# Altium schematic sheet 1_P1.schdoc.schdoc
size 309 x 223 mm; Symbol: Sheet-Symbol_A4; Device: Sheet-Symbol_A4; Company: 嘉立创EDA; Version: V1.0; Page Size: A4; @Project Name: 简易酒驾报警电路; @Page Count: 1; @Update Date: 2024-03-24; @Create Date: 2024-03-24; @Schematic Name: Schematic1; @Page No: 1; @Page Name: P1
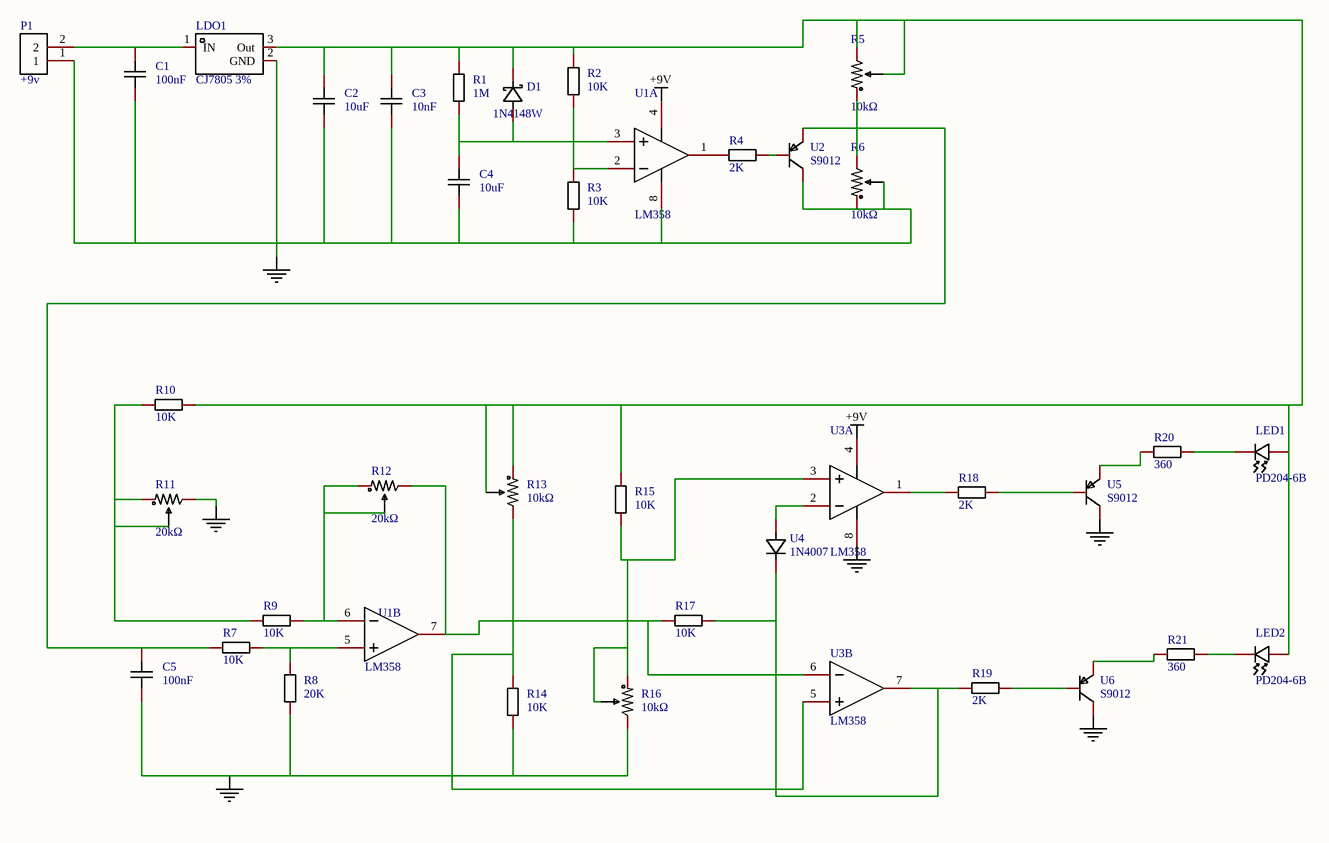
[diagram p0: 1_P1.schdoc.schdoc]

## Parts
C1  100nF  [C0603]
C2  10uF  [C0603]
C3  10nF  [C0603]
C4  10uF  [C0603]
C5  100nF  [C0603]
D1  1N4148W  [SOD-123_L2.7-W1.6-LS3.7-FD]
LDO1  CJ7805 3%  [TO-252-2_L6.6-W6.1-P4.58-LS10.1-BR-CW]
LED1  PD204-6B  [LED-TH_BD3.1-P2.54-FD]
LED2  PD204-6B  [LED-TH_BD3.1-P2.54-FD]
P1  +9v  [CONN-TH_2P-P5.00_WJ500V-5.08-2P]
R1  1M  [R0603]
R2  10K  [R0603]
R3  10K  [R0603]
R4  2K  [R0603]
R5  10kΩ  [RES-ADJ-TH_3362P]
R6  10kΩ  [RES-ADJ-TH_3362P]
R7  10K  [R0603]
R8  20K  [R0603]
R9  10K  [R0603]
R10  10K  [R0603]
R11  20kΩ  [RES-ADJ-TH_3362P]
R12  20kΩ  [RES-ADJ-TH_3362P]
R13  10kΩ  [RES-ADJ-TH_3362P]
R14  10K  [R0603]
R15  10K  [R0603]
R16  10kΩ  [RES-ADJ-TH_3362P]
R17  10K  [R0603]
R18  2K  [R0603]
R19  2K  [R0603]
R20  360  [R0603]
R21  360  [R0603]
U1  LM358  [SOP-8_L4.9-W3.9-P1.27-LS6.0-BL]  (parts A,B of 2)
U2  S9012  [SOT-23-3_L2.9-W1.4-P1.90-LS2.6-BR]
U3  LM358  [SOP-8_L4.9-W3.9-P1.27-LS6.0-BL]  (parts A,B of 2)
U4  1N4007  [SMA_L4.3-W2.6-LS5.1-RD]
U5  S9012  [SOT-23-3_L2.9-W1.4-P1.90-LS2.6-BR]
U6  S9012  [SOT-23-3_L2.9-W1.4-P1.90-LS2.6-BR]

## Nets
+9V: U1.4(VEE) U3.4(VEE)
NetC1_1: C1.1 C2.1 C3.1 C4.1 C5.1 LDO1.2(GND) P1.1 R3.1 R6.1 R6.2 R8.1 R11.3 R14.1 R16.3 U1.8(VCC) U2.3(C) U3.8(VCC) U5.3(C) U6.3(C)
NetC1_2: C1.2 LDO1.1(IN) P1.2
NetC2_2: C2.2 C3.2 D1.2(K) LDO1.3(Out) LED1.1(A) LED2.1(A) R1.2 R2.2 R5.2 R5.3 R10.2 R13.1 R13.2 R15.2
NetC4_2: C4.2 D1.1(A) R1.1 U1.3(IN1+)
NetC5_2: C5.2 R5.1 R6.3 R7.2 U2.2(E)
NetLED1_2: LED1.2(C) R20.1
NetLED2_2: LED2.2(C) R21.1
NetR2_1: R2.1 R3.2 U1.2(IN1-)
NetR4_1: R4.1 U1.1(OUT1)
NetR4_2: R4.2 U2.1(B)
NetR7_1: R7.1 R8.2 U1.5(IN2+)
NetR9_1: R9.1 R10.1 R11.1 R11.2
NetR9_2: R9.2 R12.1 R12.2 U1.6(IN2-)
NetR12_3: R12.3 R17.2 U1.7(OUT2) U3.6(IN2-)
NetR13_3: R13.3 R14.2 U3.5(IN2+)
NetR15_1: R15.1 R16.1 R16.2 U3.3(IN1+)
NetR17_1: R17.1 R19.1 U3.7(OUT2) U4.1(K)
NetR18_1: R18.1 U5.1(B)
NetR18_2: R18.2 U3.1(OUT1)
NetR19_2: R19.2 U6.1(B)
NetR20_2: R20.2 U5.2(E)
NetR21_2: R21.2 U6.2(E)
NetU3_2: U3.2(IN1-) U4.2(A)

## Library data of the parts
C1-C5 = CAP_0603: Symbol: CapAcitance; Convert to PCB: yes
D1 = 1N4148W_C7420318: Manufacturer: 宏迦橙; Add into BOM: yes; Diode Configuration: 独立式; Forward Voltage (Vf@If): 1.25V@150mA; Reverse Voltage (Vr): 100V; Average Rectified Current (Io): 150mA; Power Dissipation: 400mW; Reverse Leakage Current: 1uA@75V; Reverse Recovery Time (trr): 4ns; Description: 二极管配置:独立式;正向压降(Vf):1.25V@150mA;直流反向耐压(Vr):100V;平均整流电流(Io):150mA;功率:400mW;反向恢复时间(trr):4ns;
LDO1 = CJ7805 3%: Manufacturer: CJ(江苏长电/长晶); Add into BOM: yes; Output Type: 固定; Maximum Input Voltage: 35V; Output Voltage: 5V; MAX Output Current: 1.5A; Dropout Voltage: 2V@(1A); Output Polarity: 正极; Number of Outputs: 1; Description: 输出类型:固定;最大输入电压:35V;输出电压:5V;最大输出电流:1.5A;输出极性:正极;
LED1 LED2 = PD204-6B: Manufacturer: EVERLIGHT(亿光); Add into BOM: yes; DC Reverse Voltage: 170V; Peak  Wavelength: 940nm; Spectral Range: 840nm~1100nm; Current Dark: 10nA; Description: 反向电压:170V;接收角:-;峰值波长:940nm;频谱范围:840nm~1100nm;暗电流:10nA;
P1 = WJ500V-5.08-2P: Manufacturer: KANGNEX(康奈克斯电气); Symbol: WJ500V-5.08-2P-14-00A; Add into BOM: yes; Structure: 1x2P; Pitch: 5.08mm; Current Rating (Max): 18A; Voltage Rating (Max): 250V; Wire Gauge - AWG: 14~30; Wire Gauge - mm2: 2.5; Number of PINs Per Row: 2; Description: 结构:1x2P;间距:5.08mm;颜色:绿色;安装方式:直插;额定电流:18A;额定电压:250V;排数:1;线规 - AWG:14~30;线规 - 平方毫米:2.5;每排PIN数:2;工作温度范围:-40℃~+105℃;
R1 = 0603WAF1002T5E: Manufacturer: UNI-ROYAL(厚声); Add into BOM: yes; Tolerance: ±1%; Power(Watts): 100mW; Overload Voltage (Max): 75V; Temperature Coefficient: ±100ppm/℃; Description: 电阻类型:厚膜电阻;阻值:10kΩ;精度:±1%;功率:100mW;最大工作电压:75V;温度系数:±100ppm/℃;
R2-R4 R7-R10 R14 R15 R17-R21 = Res_0603: Symbol: 电阻; Convert to PCB: yes
R5 R6 R11-R13 R16 = 3362P-1-103: Manufacturer: BOCHEN(博晨); Symbol: 3362P-1-103_C118956; Add into BOM: yes; Tolerance: ±10%; Description: 阻值:10kΩ;精度:±10%;
U1 U3 = LM358_C5252902: Manufacturer: MSKSEMI(美森科); Add into BOM: yes; Number of Circuits: 双路; Gain Bandwidth Product(GBP): 1.2MHz; Current - Input Bias(Ib): 50nA; Voltage - Input Offset(Vos): 5mV; Common Mode Rejection Ratio (CMRR): 80dB; Supply Voltage: 3V~36V; Output Type: 差分; Supply Current: 300uA; Description: 放大器数:双路;增益带宽积(GBP):1.2MHz;输入偏置电流(Ib):50nA;输入失调电压(Vos):5mV;
U2 U5 U6 = S9012_C5204710: Manufacturer: TWGMC(台湾迪嘉); Add into BOM: yes; Description: 晶体管类型：PNP 集射极击穿电压(Vceo)：25V 集电极电流(Ic)：500mA 功率(Pd)：300mW
U4 = 1N4007: Symbol: 1N4007_C9900004759; Add into BOM: yes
